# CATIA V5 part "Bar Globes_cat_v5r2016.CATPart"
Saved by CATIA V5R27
Part number: Bar Globes
Bounding box of the stored display mesh (mm): x -5.986 to 5.986, y -4.926 to 5, z -5.986 to 5.986
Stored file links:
  E:\_Deepak\2017_Deepak\CATIA\Resources\Tutorial Files\Tutorials\c13_catia_v5_6r2016_tut\c13tut2\c13tut02.CATParts\Bar Globes_cat_v5r2016.CATPart
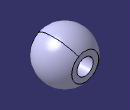
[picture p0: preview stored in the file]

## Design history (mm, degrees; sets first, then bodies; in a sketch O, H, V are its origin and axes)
Body1 (main body)
  Sketch1 on yz-plane, origin (0, 0, 0), H (0, 1, 0), V (0, 0, 1)
    arc A1 centre (0, 0) radius 6 from (6, 0) to (-6, 0) ccw
    line L1 (-6, 0) -> (6, 0)
    radius A1 = 6
    horizontal: L1 H
    coincidence: H L1
  Shaft1: profile Sketch1, axis edge of Sketch1, angle 360
  Sketch2 on yz-plane, origin (0, 0, 0), H (0, 1, 0), V (0, 0, 1)
    line L1 (-5, 7.2498) -> (5, 7.2498)
    line L2 (5, 7.2498) -> (5, -8.5554)
    line L3 (-5, -8.5554) -> (-5, 7.2498)
    point P3 (5, -8.5554)
    point P5 (5, -8.5554)
    line L4 (5, -8.5554) -> (-5, -8.5554)
    length L1 = 10
    distance V L3 = 5
    horizontal: L1 H, L4 H
    vertical: L2 V, L3 V
    coincidence: P5 P3
  Pocket1: profile Sketch2, direction (-1, 0, 0), length 20, mirrored extent, outer side
  Sketch3 on face of Pocket1, origin (0.8583, -5, 1.5686), H (1, 0, 0), V (0, 0, 1)
    point P1 (-0.8583, -1.5686)
    reference intersected line E1 through (0, -1.5686) direction (-1, 0) from xy-plane
    reference intersected line E2 through (-0.8583, 0) direction (0, 1) from yz-plane
    coincidence: P1 E1, E2 P1
  Hole1: placed by Sketch3, at (0, -5, 0) direction (0, 1, 0), diameter 4, depth 10, countersink depth 1.5, countersink angle 90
